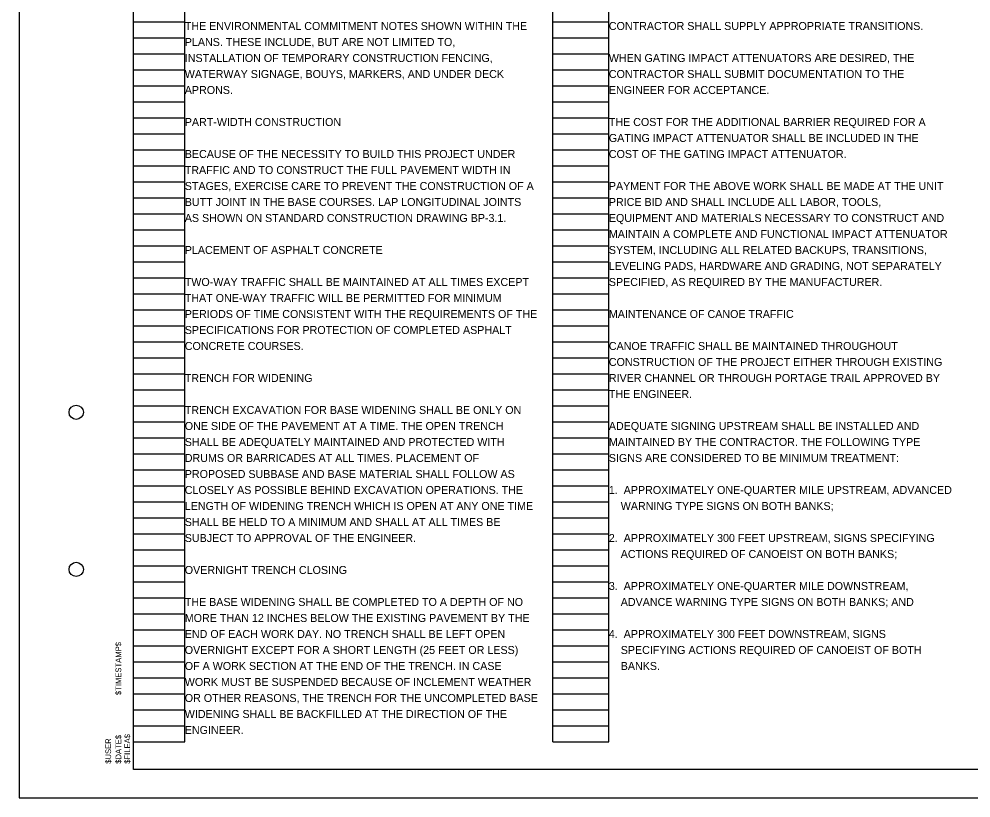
# Model space of a CAD drawing. Extents: x 0 to 34, y 0 to 27.5.
# Drawn here: x 0 to 16.66, y 0 to 13.63 of the extents above; entities that cross this region are included whole.
import ezdxf

# ---------------------------------------------------------------- set-up
doc = ezdxf.new("R2010")
doc.units = 0
for name, color, linetype in [('SC_Scratch1', 7, 'Continuous'), ('SH_Border', 7, 'Continuous'), ('SH_Cut_Line', 7, 'Continuous'), ('SH_Data', 7, 'Continuous'), ('SH_Text', 7, 'Continuous')]:
    doc.layers.add(name, color=color, linetype=linetype)

msp = doc.modelspace()

# ---------------------------------------------------------------- linework, layer by layer
at = {"layer": 'SC_Scratch1'}
for p, q in [((2, 0.98), (2, 21.14)), ((2.9, 0.98), (2.9, 21.14)), ((9.34, 0.98), (9.34, 21.14)), ((10.32, 0.98), (10.32, 21.14)), ((2, 13.58), (2.9, 13.58)), ((9.34, 13.58), (10.32, 13.58)), ((2, 13.3), (2.9, 13.3)), ((9.34, 13.3), (10.32, 13.3)), ((2, 13.02), (2.9, 13.02)), ((9.34, 13.02), (10.32, 13.02)), ((2, 12.74), (2.9, 12.74)), ((9.34, 12.74), (10.32, 12.74)), ((2, 12.46), (2.9, 12.46)), ((9.34, 12.46), (10.32, 12.46)), ((2, 12.18), (2.9, 12.18)), ((9.34, 12.18), (10.32, 12.18)), ((2, 11.9), (2.9, 11.9)), ((9.34, 11.9), (10.32, 11.9)), ((2, 11.62), (2.9, 11.62)), ((9.34, 11.62), (10.32, 11.62)), ((2, 11.34), (2.9, 11.34)), ((9.34, 11.34), (10.32, 11.34)), ((2, 11.06), (2.9, 11.06)), ((9.34, 11.06), (10.32, 11.06)), ((2, 10.78), (2.9, 10.78)), ((9.34, 10.78), (10.32, 10.78)), ((2, 10.5), (2.9, 10.5)), ((9.34, 10.5), (10.32, 10.5)), ((2, 10.22), (2.9, 10.22)), ((9.34, 10.22), (10.32, 10.22)), ((2, 9.94), (2.9, 9.94)), ((9.34, 9.94), (10.32, 9.94)), ((2, 9.66), (2.9, 9.66)), ((9.34, 9.66), (10.32, 9.66)), ((2, 9.38), (2.9, 9.38)), ((9.34, 9.38), (10.32, 9.38)), ((2, 9.1), (2.9, 9.1)), ((9.34, 9.1), (10.32, 9.1)), ((2, 8.82), (2.9, 8.82)), ((9.34, 8.82), (10.32, 8.82)), ((2, 8.54), (2.9, 8.54)), ((9.34, 8.54), (10.32, 8.54)), ((2, 8.26), (2.9, 8.26)), ((9.34, 8.26), (10.32, 8.26)), ((2, 7.98), (2.9, 7.98)), ((9.34, 7.98), (10.32, 7.98)), ((2, 7.7), (2.9, 7.7)), ((9.34, 7.7), (10.32, 7.7)), ((2, 7.42), (2.9, 7.42)), ((9.34, 7.42), (10.32, 7.42)), ((2, 7.14), (2.9, 7.14)), ((9.34, 7.14), (10.32, 7.14)), ((2, 6.86), (2.9, 6.86)), ((9.34, 6.86), (10.32, 6.86)), ((2, 6.58), (2.9, 6.58)), ((9.34, 6.58), (10.32, 6.58)), ((2, 6.3), (2.9, 6.3)), ((9.34, 6.3), (10.32, 6.3)), ((2, 6.02), (2.9, 6.02)), ((9.34, 6.02), (10.32, 6.02)), ((2, 5.74), (2.9, 5.74)), ((9.34, 5.74), (10.32, 5.74)), ((2, 5.46), (2.9, 5.46)), ((9.34, 5.46), (10.32, 5.46)), ((2, 5.18), (2.9, 5.18)), ((9.34, 5.18), (10.32, 5.18)), ((2, 4.9), (2.9, 4.9)), ((9.34, 4.9), (10.32, 4.9)), ((2, 4.62), (2.9, 4.62)), ((9.34, 4.62), (10.32, 4.62)), ((2, 4.34), (2.9, 4.34)), ((9.34, 4.34), (10.32, 4.34)), ((2, 4.06), (2.9, 4.06)), ((9.34, 4.06), (10.32, 4.06)), ((2, 3.78), (2.9, 3.78)), ((9.34, 3.78), (10.32, 3.78)), ((2, 3.5), (2.9, 3.5)), ((9.34, 3.5), (10.32, 3.5)), ((2, 3.22), (2.9, 3.22)), ((9.34, 3.22), (10.32, 3.22)), ((2, 2.94), (2.9, 2.94)), ((9.34, 2.94), (10.32, 2.94)), ((2, 2.66), (2.9, 2.66)), ((9.34, 2.66), (10.32, 2.66)), ((2, 2.38), (2.9, 2.38)), ((9.34, 2.38), (10.32, 2.38)), ((2, 2.1), (2.9, 2.1)), ((9.34, 2.1), (10.32, 2.1)), ((2, 1.82), (2.9, 1.82)), ((9.34, 1.82), (10.32, 1.82)), ((2, 1.54), (2.9, 1.54)), ((9.34, 1.54), (10.32, 1.54)), ((2, 1.26), (2.9, 1.26)), ((9.34, 1.26), (10.32, 1.26)), ((2, 0.98), (2.9, 0.98)), ((9.34, 0.98), (10.32, 0.98)), ((0, 0), (0, 0))]:
    msp.add_line(p, q, dxfattribs=at)
at = {"layer": 'SH_Border'}
msp.add_lwpolyline([(2, 21.5), (33.5, 21.5), (33.5, 0.5), (2, 0.5)], close=True, dxfattribs=at)
for centre in [(1, 6.75), (1, 4)]:
    msp.add_circle(centre, 0.125, dxfattribs=at)
at = {"layer": 'SH_Cut_Line'}
msp.add_lwpolyline([(0, 0), (34, 0), (34, 22), (0, 22)], close=True, dxfattribs=at)

# ---------------------------------------------------------------- texts
at = {"layer": 'SH_Data'}
for s, p in [('$TIMESTAMP$', (1.788, 1.8)), ('$USER', (1.611, 0.598)), ('$DATE$', (1.788, 0.598)), ('$FILEA$', (1.944, 0.598))]:
    msp.add_text(s, height=0.1, rotation=89.9931, dxfattribs=at).set_placement(p)
at = {"layer": 'SH_Text'}
for s, p in [('THE ENVIRONMENTAL COMMITMENT NOTES SHOWN WITHIN THE ', (2.9, 13.44)), ('CONTRACTOR SHALL SUPPLY APPROPRIATE TRANSITIONS.', (10.32, 13.44)), ('PLANS. THESE INCLUDE, BUT ARE NOT LIMITED TO, ', (2.9, 13.16)), ('INSTALLATION OF TEMPORARY CONSTRUCTION FENCING, ', (2.9, 12.88)), ('WHEN GATING IMPACT ATTENUATORS ARE DESIRED, THE ', (10.32, 12.88)), ('WATERWAY SIGNAGE, BOUYS, MARKERS, AND UNDER DECK ', (2.9, 12.6)), ('CONTRACTOR SHALL SUBMIT DOCUMENTATION TO THE ', (10.32, 12.6)), ('APRONS. ', (2.9, 12.32)), ('ENGINEER FOR ACCEPTANCE.', (10.32, 12.32)), ('PART-WIDTH CONSTRUCTION', (2.9, 11.76)), ('THE COST FOR THE ADDITIONAL BARRIER REQUIRED FOR A ', (10.32, 11.76)), ('GATING IMPACT ATTENUATOR SHALL BE INCLUDED IN THE ', (10.32, 11.48)), ('BECAUSE OF THE NECESSITY TO BUILD THIS PROJECT UNDER ', (2.9, 11.2)), ('COST OF THE GATING IMPACT ATTENUATOR.', (10.32, 11.2)), ('TRAFFIC AND TO CONSTRUCT THE FULL PAVEMENT WIDTH IN ', (2.9, 10.92)), ('STAGES, EXERCISE CARE TO PREVENT THE CONSTRUCTION OF A ', (2.9, 10.64)), ('PAYMENT FOR THE ABOVE WORK SHALL BE MADE AT THE UNIT ', (10.32, 10.64)), ('BUTT JOINT IN THE BASE COURSES. LAP LONGITUDINAL JOINTS ', (2.9, 10.36)), ('PRICE BID AND SHALL INCLUDE ALL LABOR, TOOLS, ', (10.32, 10.36)), ('AS SHOWN ON STANDARD CONSTRUCTION DRAWING BP-3.1.', (2.9, 10.08)), ('EQUIPMENT AND MATERIALS NECESSARY TO CONSTRUCT AND ', (10.32, 10.08)), ('MAINTAIN A COMPLETE AND FUNCTIONAL IMPACT ATTENUATOR ', (10.32, 9.8)), ('PLACEMENT OF ASPHALT CONCRETE', (2.9, 9.52)), ('SYSTEM, INCLUDING ALL RELATED BACKUPS, TRANSITIONS, ', (10.32, 9.52)), ('LEVELING PADS, HARDWARE AND GRADING, NOT SEPARATELY ', (10.32, 9.24)), ('TWO-WAY TRAFFIC SHALL BE MAINTAINED AT ALL TIMES EXCEPT ', (2.9, 8.96)), ('SPECIFIED, AS REQUIRED BY THE MANUFACTURER.', (10.32, 8.96)), ('THAT ONE-WAY TRAFFIC WILL BE PERMITTED FOR MINIMUM ', (2.9, 8.68)), ('PERIODS OF TIME CONSISTENT WITH THE REQUIREMENTS OF THE ', (2.9, 8.4)), ('MAINTENANCE OF CANOE TRAFFIC', (10.32, 8.4)), ('SPECIFICATIONS FOR PROTECTION OF COMPLETED ASPHALT ', (2.9, 8.12)), ('CONCRETE COURSES.', (2.9, 7.84)), ('CANOE TRAFFIC SHALL BE MAINTAINED THROUGHOUT ', (10.32, 7.84)), ('CONSTRUCTION OF THE PROJECT EITHER THROUGH EXISTING ', (10.32, 7.56)), ('TRENCH FOR WIDENING', (2.9, 7.28)), ('RIVER CHANNEL OR THROUGH PORTAGE TRAIL APPROVED BY ', (10.32, 7.28)), ('THE ENGINEER.', (10.32, 7)), ('TRENCH EXCAVATION FOR BASE WIDENING SHALL BE ONLY ON ', (2.9, 6.72)), ('ONE SIDE OF THE PAVEMENT AT A TIME. THE OPEN TRENCH ', (2.9, 6.44)), ('ADEQUATE SIGNING UPSTREAM SHALL BE INSTALLED AND ', (10.32, 6.44)), ('SHALL BE ADEQUATELY MAINTAINED AND PROTECTED WITH ', (2.9, 6.16)), ('MAINTAINED BY THE CONTRACTOR. THE FOLLOWING TYPE ', (10.32, 6.16)), ('DRUMS OR BARRICADES AT ALL TIMES. PLACEMENT OF ', (2.9, 5.88)), ('SIGNS ARE CONSIDERED TO BE MINIMUM TREATMENT:', (10.32, 5.88)), ('PROPOSED SUBBASE AND BASE MATERIAL SHALL FOLLOW AS ', (2.9, 5.6)), ('CLOSELY AS POSSIBLE BEHIND EXCAVATION OPERATIONS. THE ', (2.9, 5.32)), ('1.  APPROXIMATELY ONE-QUARTER MILE UPSTREAM, ADVANCED', (10.32, 5.32)), ('LENGTH OF WIDENING TRENCH WHICH IS OPEN AT ANY ONE TIME ', (2.9, 5.04)), ('    WARNING TYPE SIGNS ON BOTH BANKS;', (10.32, 5.04)), ('SHALL BE HELD TO A MINIMUM AND SHALL AT ALL TIMES BE ', (2.9, 4.76)), ('SUBJECT TO APPROVAL OF THE ENGINEER.', (2.9, 4.48)), ('2.  APPROXIMATELY 300 FEET UPSTREAM, SIGNS SPECIFYING', (10.32, 4.48)), ('    ACTIONS REQUIRED OF CANOEIST ON BOTH BANKS;', (10.32, 4.2)), ('OVERNIGHT TRENCH CLOSING', (2.9, 3.92)), ('3.  APPROXIMATELY ONE-QUARTER MILE DOWNSTREAM,', (10.32, 3.64)), ('THE BASE WIDENING SHALL BE COMPLETED TO A DEPTH OF NO ', (2.9, 3.36)), ('    ADVANCE WARNING TYPE SIGNS ON BOTH BANKS; AND', (10.32, 3.36)), ('MORE THAN 12 INCHES BELOW THE EXISTING PAVEMENT BY THE ', (2.9, 3.08)), ('END OF EACH WORK DAY. NO TRENCH SHALL BE LEFT OPEN ', (2.9, 2.8)), ('4.  APPROXIMATELY 300 FEET DOWNSTREAM, SIGNS', (10.32, 2.8)), ('OVERNIGHT EXCEPT FOR A SHORT LENGTH (25 FEET OR LESS) ', (2.9, 2.52)), ('    SPECIFYING ACTIONS REQUIRED OF CANOEIST OF BOTH', (10.32, 2.52)), ('OF A WORK SECTION AT THE END OF THE TRENCH. IN CASE ', (2.9, 2.24)), ('    BANKS.', (10.32, 2.24)), ('WORK MUST BE SUSPENDED BECAUSE OF INCLEMENT WEATHER ', (2.9, 1.96)), ('OR OTHER REASONS, THE TRENCH FOR THE UNCOMPLETED BASE ', (2.9, 1.68)), ('WIDENING SHALL BE BACKFILLED AT THE DIRECTION OF THE ', (2.9, 1.4)), ('ENGINEER.', (2.9, 1.12))]:
    msp.add_text(s, height=0.14, dxfattribs=at).set_placement(p)

doc.saveas('drawing.dxf')
